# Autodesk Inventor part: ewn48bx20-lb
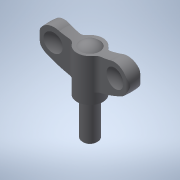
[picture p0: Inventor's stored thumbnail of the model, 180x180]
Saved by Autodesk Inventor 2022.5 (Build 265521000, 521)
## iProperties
Created: 2017-05
Part Number: ewn48bx20-lb
Material: 一般
Document SubType Name: Modeling
Designer: imaocorp
Density: 1 g/cm^3
Appearance: 既定
Author: imaocorp
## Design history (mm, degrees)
node "ewn48bx20-lb.x_t1"
node "ewn48bx20-lb"
node "Base1"
